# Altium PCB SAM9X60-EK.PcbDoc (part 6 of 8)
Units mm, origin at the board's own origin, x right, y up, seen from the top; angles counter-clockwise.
Board outline 150 x 125 mm, 4 copper layers (L1 - Top Layer, L2 - GND, L3 - PWR, L4 - Bottom Layer), stack 1.52 mm thick; 566 components, 500 nets, 2132 pads, 1038 vias.
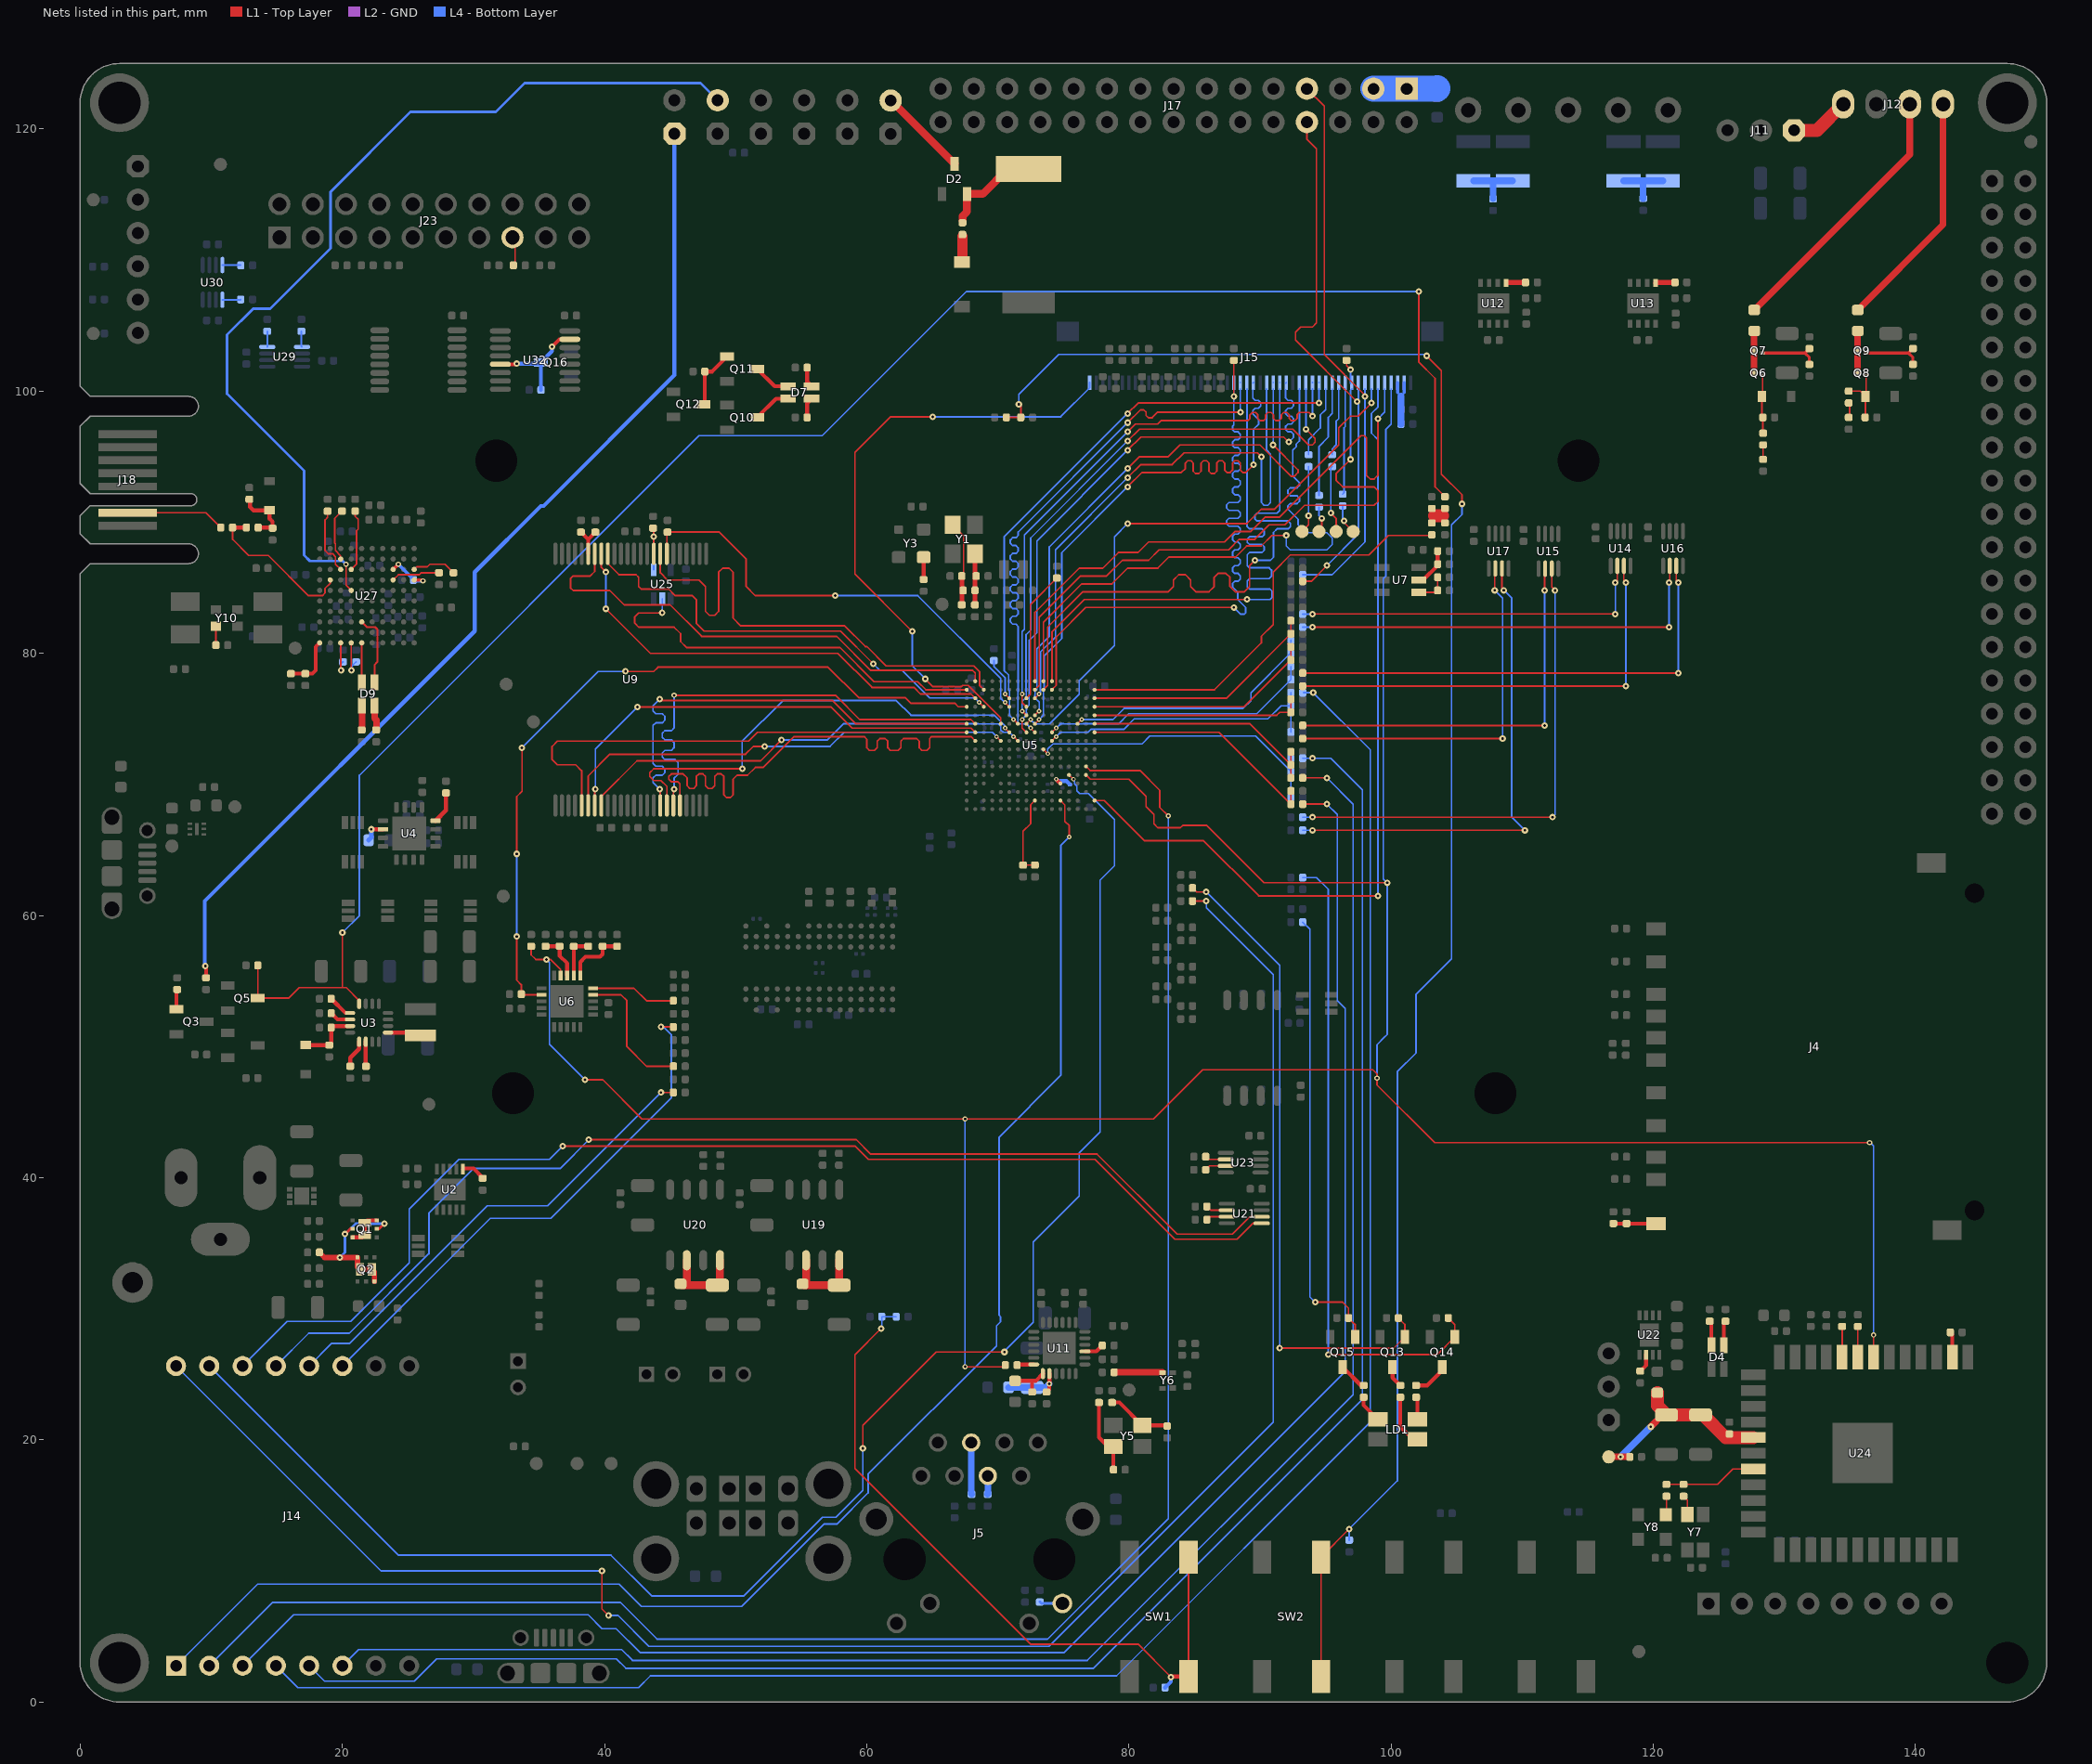
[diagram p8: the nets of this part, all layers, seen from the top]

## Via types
v1: diameter 0.5, hole 0.2, L1 - Top Layer to L4 - Bottom Layer, tented both sides, 483 vias
v2: diameter 0.5, hole 0.2, L1 - Top Layer to L4 - Bottom Layer, 268 vias
v3: diameter 0.4, hole 0.2, L1 - Top Layer to L4 - Bottom Layer, tented both sides, 145 vias
v4: diameter 0.35, hole 0.15, L1 - Top Layer to L4 - Bottom Layer, tented both sides, 121 vias
v5: diameter 0.55, hole 0.3, L1 - Top Layer to L4 - Bottom Layer, tented bottom, 16 vias
v6: diameter 0.559, hole 0.305, L1 - Top Layer to L4 - Bottom Layer, 5 vias

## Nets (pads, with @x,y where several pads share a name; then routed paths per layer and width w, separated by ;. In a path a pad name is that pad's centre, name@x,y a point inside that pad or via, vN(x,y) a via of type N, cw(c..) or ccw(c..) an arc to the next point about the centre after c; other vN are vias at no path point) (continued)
LCD_D16_ISI_nRST_PC16: J15.23 R212.1 U5.R6 | length 49.8
  L1 - Top Layer w0.125: U5.R6@74.125,77.225 74.45,77.55 74.45,81.25 76.7,83.5 v1(88,83.5) ; v1(88,99.6) R212.1@88,102.35
  L4 - Bottom Layer w0.125: v1(88,83.5) 88.5,83 88.8,83 88.9,83.1 88.9,83.5 88.3,84.1 88.3,84.675 87.9,85.075 87.9,85.325 88.075,85.5 88.325,85.5 88.5,85.675 88.5,85.925 88.325,86.1 88.075,86.1 87.9,86.275 87.9,86.525 88.075,86.7 88.325,86.7 88.5,86.875 88.5,87.125 88.325,87.3 88.075,87.3 87.9,87.475 87.9,87.725 88.075,87.9 88.325,87.9 88.5,88.075 88.5,88.325 88.325,88.5 88.075,88.5 87.9,88.675 87.9,88.925 88.075,89.1 88.325,89.1 88.5,89.275 88.5,89.525 88.325,89.7 87.625,89.7 87.45,89.875 87.45,90.125 87.625,90.3 88.325,90.3 88.5,90.475 88.5,90.725 88.325,90.9 87.625,90.9 87.45,91.075 87.45,91.325 87.625,91.5 88.325,91.5 88.5,91.675 88.5,91.925 88.325,92.1 88.075,92.1 87.9,92.275 87.9,92.525 88.075,92.7 88.325,92.7 88.5,92.875 88.5,93.125 88.325,93.3 88.075,93.3 87.9,93.475 87.9,93.725 88.075,93.9 88.325,93.9 88.5,94.075 88.5,94.325 88.325,94.5 88.075,94.5 87.9,94.675 87.9,94.925 88.075,95.1 88.325,95.1 88.5,95.275 88.5,95.525 88.325,95.7 88.075,95.7 87.9,95.875 87.9,96.125 88.075,96.3 88.325,96.3 88.5,96.475 88.5,96.725 88.325,96.9 88.075,96.9 87.9,97.075 87.9,97.325 88,97.425 J15.23@88,100.159
LCD_D17_PC17: J15.24 U5.K8 | length 44
  L1 - Top Layer w0.125: v4(72.5,74.3) U5.K8@72.825,73.975 ; v1(79.9,97.6) 80.875,98.575 81.125,98.575 81.3,98.4 81.3,98.15 81.475,97.975 81.775,97.975 82.2,98.4 v1(88.5,98.4)
  L4 - Bottom Layer w0.1: 71.55,77.1 71.525,77.075 71.525,74.725 71.65,74.6 72.2,74.6 v4(72.5,74.3)
  L4 - Bottom Layer w0.125: 71.55,77.1 71.55,82.05 71.375,82.225 71.125,82.225 70.95,82.4 70.95,82.65 71.125,82.825 71.375,82.825 71.55,83 71.55,83.25 71.375,83.425 71.125,83.425 70.95,83.6 70.95,83.85 71.125,84.025 71.375,84.025 71.55,84.2 71.55,84.45 71.375,84.625 71.125,84.625 70.95,84.8 70.95,85.05 71.125,85.225 71.375,85.225 71.55,85.4 71.55,85.65 71.375,85.825 71.125,85.825 70.95,86 70.95,86.25 71.125,86.425 71.375,86.425 71.55,86.6 71.55,86.85 71.375,87.025 71.125,87.025 70.95,87.2 70.95,87.45 71.125,87.625 71.375,87.625 71.55,87.8 71.55,88.05 71.375,88.225 71.125,88.225 70.95,88.4 70.95,88.65 71.125,88.825 71.375,88.825 71.55,89 71.55,89.25 v1(79.9,97.6) ; v1(88.5,98.4) J15.24@88.5,100.159
LCD_D18_PC18: J15.25 U5.T6 | length 46.9
  L1 - Top Layer w0.125: U5.T6@74.125,77.875 74.125,81.625 76.6,84.1 v1@89,84.1
  L4 - Bottom Layer w0.125: v1(89,84.125) 89.025,84.1 90.75,84.1 90.925,84.275 90.925,84.725 90.75,84.9 89.2,84.9 89.025,85.075 89.025,85.525 89.2,85.7 90.125,85.7 90.7,85.7 90.875,85.875 90.875,86.35 90.7,86.525 89.2,86.525 89.025,86.7 89.025,87.525 89.2,87.7 90.125,87.7 90.15,87.7 90.325,87.875 90.325,88.125 90.15,88.3 89.2,88.3 89.025,88.475 89.025,88.725 89.2,88.9 90.125,88.9 90.15,88.9 90.325,89.075 90.325,89.325 90.15,89.5 89.2,89.5 89,89.7 J15.25@89,100.159
LCD_D19_PC19: J15.26 U5.L8 | length 44
  L1 - Top Layer w0.125: U5.L8@72.825,74.625 v4(73.15,74.95) ; v1(79.9,92.7) 81,93.8 84,93.8 84.3,94.1 84.3,94.525 84.475,94.7 84.725,94.7 84.9,94.525 84.9,94.25 84.9,93.9 85.075,93.725 85.325,93.725 85.5,93.9 85.5,94.25 85.5,94.525 85.675,94.7 85.925,94.7 86.1,94.525 86.1,94.25 86.1,93.9 86.275,93.725 86.525,93.725 86.7,93.9 86.7,94.25 86.7,94.525 86.875,94.7 87.125,94.7 87.3,94.525 87.3,94.25 87.3,93.975 87.475,93.8 87.725,93.8 87.9,93.975 87.9,94.25 87.9,94.525 88.075,94.7 88.325,94.7 88.5,94.525 88.5,94.25 88.5,93.975 88.675,93.8 88.925,93.8 89.5,94.375 v1(89.5,94.4)
  L4 - Bottom Layer w0.1: 73.475,75.275 73.475,76.991
  L4 - Bottom Layer w0.125: v4(73.15,74.95) 73.475,75.275 ; 73.475,76.991 73.475,77.125 73.525,77.175 73.525,79.775 74.875,81.125 74.875,87.675 v1(79.9,92.7) ; 89.45,100.109 89.45,99.475 89.625,99.3 89.875,99.3 90.05,99.125 90.05,98.875 89.875,98.7 89.625,98.7 89.45,98.525 89.45,98.275 89.9,97.825 89.9,97.5 89.5,97.1 v1(89.5,94.4) ; J15.26@89.45,100.609 J15.26@89.5,100.659
LCD_D20_PC20: J15.28 U5.P8 | length 44
  L1 - Top Layer w0.125: U5.P8@72.825,76.575 v4(73.15,76.9) ; v1(79.9,93.4) 80.9,94.4 83.3,94.4 84.2,95.3 89.8,95.3 v1(90.1,95)
  L4 - Bottom Layer w0.125: v4(73.15,76.9) 73.25,77 73.25,80.1 74.4,81.25 74.4,87.9 v1(79.9,93.4) ; v1(90.1,95) 90.1,91.5 90.3,91.3 90.6,91.3 90.8,91.5 90.8,95.2 90.5,95.5 J15.28@90.5,100.159
LCD_D21_PC21: J15.29 U5.M8 | length 44
  L1 - Top Layer w0.125: U5.M8@72.825,75.275 v4(73.15,75.6) ; v1(79.9,94.1) 80.8,95 83,95 83.9,95.9 90,95.9 92.4,93.5 92.6,93.5 92.9,93.8 92.9,94 v1(91,95.9)
  L4 - Bottom Layer w0.1: 72.825,76.809 72.825,77.1
  L4 - Bottom Layer w0.125: 72.825,76.809 72.825,76.6 73.15,76.275 v4(73.15,75.6) ; 72.825,77.1 72.975,77.25 72.975,80.35 73.925,81.3 73.925,88.125 v1(79.9,94.1) ; v1(91,95.9) J15.29@91,100.159
LCD_D22_PC22: J15.30 U5.R7 | length 47
  L1 - Top Layer w0.125: U5.R7@73.475,77.225 73.8,77.55 73.8,82 76.5,84.7 83,84.7 83.4,85.1 83.4,85.6 83.8,86 84.3,86 84.7,85.6 84.7,85.1 85.1,84.7 86.1,84.7 86.5,85.1 86.5,85.8 86.8,86.1 87.4,86.1 87.7,85.8 87.7,85.1 88.1,84.7 88.8,84.7 89.2,85.1 89.2,86.7 v1(89.6,87.1)
  L4 - Bottom Layer w0.125: v1(89.6,87.1) 90.8,87.1 91.025,87.325 91.025,89.225 91.3,89.5 92.125,89.5 92.15,89.5 92.325,89.675 92.325,89.925 92.15,90.1 91.3,90.1 89.775,90.1 89.6,90.275 89.6,90.525 89.775,90.7 90.375,90.7 91.3,90.7 91.5,90.9 J15.30@91.5,100.159
LCD_D23_PC23: J15.31 U5.K9 | length 44
  L1 - Top Layer w0.125: v4(71.85,74.95) 71.85,74.3 U5.K9@72.175,73.975 ; v1(79.9,95.5) 80.9,96.5 91.8,96.5 92.175,96.125 v1(92.2,96.125)
  L4 - Bottom Layer w0.1: 72.175,75.509 72.175,75.691 ; 72.375,76.592 72.375,77.325 72.4,77.35
  L4 - Bottom Layer w0.125: v4(71.85,74.95) 72.175,75.275 72.175,75.509 ; 72.175,75.691 72.175,75.85 72.375,76.05 72.375,76.592 ; 72.4,77.35 72.4,81 72.975,81.575 72.975,88.575 v1(79.9,95.5) ; 91.95,100.109 91.95,99.475 92.125,99.3 92.375,99.3 92.55,99.125 92.55,98.875 92.375,98.7 92.125,98.7 91.95,98.525 91.95,98.275 92.125,98.1 92.375,98.1 92.55,97.925 92.55,97.675 92.375,97.5 92.125,97.5 91.95,97.325 91.95,97.075 92.125,96.9 92.375,96.9 92.55,96.725 92.55,96.475 v1(92.2,96.125) ; J15.31@91.95,100.609 J15.31@92,100.659
LCD_DATA_ENABLE_PC29: J15.36 U5.L10 | length 44
  L1 - Top Layer w0.125: v4(71.2,74.95) U5.L10@71.525,74.625 ; v1(79.9,98.3) 80.7,99.1 v1(94.5,99.1)
  L4 - Bottom Layer w0.1: 70.875,75.275 70.875,77.187
  L4 - Bottom Layer w0.125: 70.863,77.187 70.825,77.225 70.825,78.35 70.475,78.7 70.475,88.875 v1(79.9,98.3) ; 70.875,75.275 v4(71.2,74.95) ; v1(94.5,99.1) J15.36@94.5,100.159
LCD_HSYNC/WE_PC28: J15.35 U5.N9 | length 44
  L1 - Top Layer w0.125: v4(71.85,76.9) 71.85,76.25 U5.N9@72.175,75.925 ; v1(79.9,96.9) 80.5,97.5 82.2,97.5 82.45,97.75 89.05,97.75 89.225,97.925 89.225,98.2 89.4,98.375 89.65,98.375 89.825,98.2 89.825,97.925 90,97.75 90.25,97.75 90.425,97.925 90.425,98.2 90.6,98.375 90.85,98.375 91.025,98.2 91.025,97.925 91.2,97.75 91.45,97.75 91.625,97.925 91.625,98.2 91.8,98.375 92.05,98.375 92.225,98.2 92.225,97.925 92.4,97.75 92.65,97.75 92.825,97.925 92.825,98.2 93,98.375 93.725,98.375 v1(94,98.1)
  L4 - Bottom Layer w0.125: v4(71.85,76.9) 71.85,80.1 71.85,81.675 72.025,81.85 72.025,89.025 v1(79.9,96.9) ; v1(94,98.1) J15.35@94,100.159
LCD_ID_PD14: J15.1 U5.L12 | length 47.4
  L1 - Top Layer w0.125: v1(63.475,81.675) 59.1,86.05 59.1,95.325 61.825,98.05 v1(65.025,98.05) ; v1(64.475,78.05) 64.475,78.025 65.025,77.475 67.25,77.475 67.325,77.55 67.75,77.55 70.225,75.075 U5.L12@70.225,74.625
  L4 - Bottom Layer w0.125: v1@63.475,81.725 v1(63.475,81.675) 63.475,79.05 v1(64.475,78.05) ; v1(65.025,98.05) 74.8,98.05 77,100.25 J15.1@77,100.659
LCD_IRQ1_PC25: J15.44 U5.L9 | length 44
  L1 - Top Layer w0.125: U5.L9@72.175,74.625 v4(72.5,74.95) ; v1(79.9,89.9) 89,89.9 90.1,91 91.1,91 96,95.9 96,97.2 96.9,98.1 97.5,98.1 v1(98.5,99.1)
  L4 - Bottom Layer w0.1: v4(72.5,74.95) 72.825,74.625 73.935,74.625 76.2,76.89
  L4 - Bottom Layer w0.125: 76.2,76.89 76.2,77.9 78.9,80.6 78.9,88.9 v1(79.9,89.9) ; v1(98.5,99.1) J15.44@98.5,100.159
LCD_IRQ2_PB17: J15.45 U5.B1 | length 63.7
  L1 - Top Layer w0.125: U5.B1@77.375,68.775 78.125,68.775 81.2,65.7 85.7,65.7 89.9,61.5 v1(99,61.5)
  L4 - Bottom Layer w0.125: v1(99,61.5) 99,96.3 98.5,96.8 98.5,98.3 99,98.8 J15.45@99,100.159
LCD_ISI_ENABLE_PC24: J15.41 R213.2 U5.R8 | length 48.8
  L1 - Top Layer w0.125: U5.R8@72.825,77.225 73.15,77.55 73.15,82.75 76.3,85.9 78.3,85.9 79.5,87.1 81.5,87.1 82.3,87.9 87.6,87.9 88.4,88.7 89.6,88.7 90.7,89.8 91.9,89.8 93.4,91.3 98.7,91.3 99,91.6 99,92.4 98.7,92.7 96.3,92.7 95.8,93.2 95.8,93.7 v1(96.9,94.8) ; R213.2@96.6,102.35 96.6,101.941 v1(96.9,101.641)
  L4 - Bottom Layer w0.125: v1(96.9,94.8) 96.9,100.059 J15.41@97,100.159 ; J15.41@96.9,100.6 v1(96.9,101.641)
LCD_ISI_TWCK: J15.43 J17.7 R73.2 | length 42.8
  L1 - Top Layer w0.125: J17.7@93.568,123.07 94.9,121.738 94.9,102.8 98,99.7 v1(98,99.6)
  L4 - Bottom Layer w0.125: R73.2@93.25,86 95.5,86 98,88.5 J15.43@98,100.159
LCD_ISI_TWD: J15.42 J17.8 R64.2 | length 41.6
  L1 - Top Layer w0.125: R64.2@93.25,85.5 93.9,85.5 v2(95.1,86.7) ; J17.8@93.568,120.53 93.568,119.232 94.3,118.5 94.3,105.2 94,104.9 93.1,104.9 92.7,104.5 92.7,103.9 v1(97.39,99.209)
  L4 - Bottom Layer w0.125: v2(95.1,86.7) 97.5,89.1 J15.42@97.5,100.159
LCD_PCLK_PC30: J15.33 U5.T7 | length 47
  L1 - Top Layer w0.125: U5.T7@73.475,77.875 73.475,82.375 76.4,85.3 78.7,85.3 79.9,86.5 82.2,86.5 83.05,87.35 88.125,87.35 88.975,88.2 90.1,88.2 90.896,88.996 v1(92,88.996)
  L4 - Bottom Layer w0.125: v1(92,88.996) 92,88.2 92.3,87.9 95.1,87.9 95.5,88.3 95.5,88.8 95.1,89.2 93.5,89.2 92.9,89.8 92.9,90.225 92.125,91 92.125,91.25 92.3,91.425 92.825,91.425 93,91.6 93,91.85 92.825,92.025 92.3,92.025 92.125,92.2 92.125,92.45 92.3,92.625 92.825,92.625 93,92.8 93,93.025 92.5,93.525 92.5,95.5 92.762,95.762 92.762,95.963 93,96.2 J15.33@93,100.159
LCD_PWM_PC26: J15.46 U5.T8 | length 46.9
  L1 - Top Layer w0.125: U5.T8@72.825,77.875 72.825,83.125 76.2,86.5 78,86.5 79.2,87.7 80.7,87.7 81.5,88.5 87.3,88.5 88.1,89.3 89.3,89.3 90.4,90.4 91.5,90.4 97.7,96.6 97.95,96.6 98.125,96.425 98.125,93.575 98.4,93.3 98.7,93.3 99,93.6 v1(99,97.9)
  L4 - Bottom Layer w0.125: v1(99,97.9) 99.5,98.4 J15.46@99.5,100.159
LCD_VSYNC/CS_PC27: J15.34 U5.M9 | length 44
  L1 - Top Layer w0.125: v4@71.875,75.575 U5.M9@72.175,75.275 ; v1(79.9,96.2) 80.8,97.1 92.5,97.1 93.7,95.9 94,95.9 94.2,96.1 94.2,96.4 v1(93.5,97.1)
  L4 - Bottom Layer w0.1: 72.15,77.1 72.175,77.075 72.175,76.664 72.156,76.646
  L4 - Bottom Layer w0.125: v4(71.85,75.6) 71.85,76.339 72.156,76.646 ; 72.15,77.1 72.15,81.425 72.5,81.775 72.5,88.8 v1(79.9,96.2) ; v1(93.5,97.1) J15.34@93.5,100.159
LED1_3U: D9.2 U27.E3 | length 5.6
  L1 - Top Layer w0.15: U27.E3@21.475,82.4 21.875,82 22.5,82 22.675,81.825 22.675,79.35 22.45,79.125 D9.2@22.45,77.8
LED2_3U: D9.3 U27.E1 | length 3
  L1 - Top Layer w0.15: U27.E1@21.475,80.8 21.475,77.825 D9.3@21.5,77.8
LEFT_N: FB11.2 J12.1 | length 18.4
  L1 - Top Layer w0.5: FB11.2@135.6,106.2 142.1,112.7 J12.1@142.1,121.9
LEFT_P: FB10.2 J12.2 | length 20.6
  L1 - Top Layer w0.5: FB10.2@127.7,106.2 139.56,118.06 J12.2@139.56,121.9
MBUS_AD4_PB15: J14.1 U5.B5 | length 119.2
  L1 - Top Layer w0.125: U5.B5@74.775,68.775 75.112,68.438 75.112,67.188 75.45,66.85 v4(75.45,66)
  L4 - Bottom Layer w0.125: J14.1@7.31,2.77 13.54,9 41.1,9 42.8,7.3 50.45,7.3 56.725,13.575 57.725,13.575 60.1,15.95 60.1,17.375 69.9,27.175 69.9,28.7 70.2,29 70.2,29.4 70.1,29.5 70.1,43.1 74.8,47.8 74.8,65.35 v4(75.45,66)
MBUS_INT_PB18: J14.15 U5.E4 | length 127.8
  L1 - Top Layer w0.125: v1(59.7,19.35) 59.7,21.1 65.3,26.7 v1(70.5,26.7) ; U5.E4@75.425,70.725 v4@75.725,70.425
  L4 - Bottom Layer w0.125: J14.15@9.85,25.63 24.28,11.2 40.49,11.2 43.59,8.1 50.625,8.1 56.625,14.1 57.65,14.1 59.7,16.15 v1(59.7,19.35) ; v1(70.5,26.7) 70.5,26.781 72.7,28.981 72.7,35.1 76.2,38.6 76.2,41.9 77.8,43.5 77.8,62.7 78.9,63.8 78.9,67.325 76.925,69.3 76.25,69.3 76.025,69.525 76.025,69.875 75.85,70.05 75.85,70.25 v4@75.725,70.375
  other v4: 75.775,70.4
MBUS_MISO_PA11: J14.5 R50.1 | length 142.4
  L4 - Bottom Layer w0.125: J14.5@17.47,2.77 18.64,1.6 25.5,1.6 27.2,3.3 40.9,3.3 41.625,2.575 43,2.575 77.293,2.575 97.8,23.082 97.8,64.7 97.8,69.6 95.4,72 v2(94.001,72) R50.1@93.251,72
MBUS_MOSI_PA12: J14.6 R53.1 | length 136.1
  L1 - Top Layer w0.125: R53.1@93.251,70.5 v2(95.1,70.5)
  L4 - Bottom Layer w0.125: J14.6@20.01,2.77 21.24,4 41.3,4 42.125,3.175 43.2,3.175 76.825,3.175 97.1,23.45 97.1,68.5 v2(95.1,70.5)
MBUS_NPCS0_PA14: J14.3 R58.1 | length 141.5
  L1 - Top Layer w0.125: R58.1@93.251,68.5 v2(95.1,68.5)
  L4 - Bottom Layer w0.125: J14.3@12.39,2.77 16.27,6.65 38.75,6.65 39.8,5.6 40.875,5.6 42.7,3.775 75.075,3.775 96.5,25.2 96.5,52.9 95.9,53.5 95.9,67.7 v2(95.1,68.5)
MBUS_PWM_PB13: J14.16 R65.2 | length 144.2
  L1 - Top Layer w0.125: v1(39.8,10) 39.8,7.1 v1(40.3,6.6) ; R65.2@84.85,61.1 v2(85.9,61.1)
  L4 - Bottom Layer w0.125: J14.16@7.31,25.63 22.94,10 v1(39.8,10) ; v1(40.3,6.6) 41.025,6.6 43.375,4.25 73.9,4.25 91,21.35 91,55.5 85.9,60.6 v2(85.9,61.1)
MBUS_RST_PB14: J14.2 U5.F2 | length 142.3
  L1 - Top Layer w0.125: U5.F2@76.725,71.375 77.039,71.061 80.839,71.061 82.348,69.552 82.348,68.252 v3(83,67.6)
  L4 - Bottom Layer w0.125: J14.2@9.85,2.77 14.68,7.6 41.2,7.6 44,4.8 73.8,4.8 83,14 v3(83,67.6)
MBUS_RX: J14.14 U21.5 | length 90.5
  L1 - Top Layer w0.125: v1(36.8,42.4) 38.025,42.4 59.134,42.4 60.134,41.4 77.4,41.4 83.5,35.3 88.231,35.3 89.45,36.519 U21.5@90.125,36.519
  L4 - Bottom Layer w0.125: J14.14@12.39,25.63 15.8,29.04 20.64,29.04 25.1,33.5 25.1,37.6 28.9,41.4 35.8,41.4 v1(36.8,42.4)
MBUS_SPCK_PA13: J14.4 R56.1 | length 150.8
  L4 - Bottom Layer w0.125: J14.4@14.93,2.77 16.6,1.1 42.6,1.1 43.5,2 79.052,2 98.4,21.348 98.4,67.4 98.4,72.651 v2(94.051,77) R56.1@93.301,77
MBUS_TWCK: J14.12 R95.2 | length 36.4
  L1 - Top Layer w0.125: v2(44.3,46.5) R95.2@45.25,46.5
  L4 - Bottom Layer w0.125: J14.12@17.47,25.63 19.2,27.36 20.56,27.36 31.05,37.85 35.65,37.85 v2(44.3,46.5)
MBUS_TWD: J14.11 R90.2 | length 40.4
  L1 - Top Layer w0.125: v2(44.3,51.5) R90.2@45.25,51.5
  L4 - Bottom Layer w0.125: J14.11@20.01,25.63 31.28,36.9 35.9,36.9 45.1,46.1 45.1,50.9 44.5,51.5 v2(44.3,51.5)
MBUS_TX: J14.13 U21.6 | length 87.7
  L1 - Top Layer w0.125: v1(38.8,42.9) 59.2,42.9 60.3,41.8 77.566,41.8 83.666,35.7 87.881,35.7 89.2,37.019 U21.6@90.125,37.019
  L4 - Bottom Layer w0.125: J14.13@14.93,25.63 17.435,28.135 20.535,28.135 26.6,34.2 26.6,37.3 30,40.7 36.6,40.7 v1(38.8,42.9)
MCP23008_INT_PD17: R33.1 U5.N16 U6.7 | length 58.4
  L1 - Top Layer w0.125: v1(33.3,58.4) 33.3,55.075 33.65,54.725 R33.1@33.65,54 33.7,53.95 U6.7@35.185,53.95 ; v1(33.3,64.7) 33.3,69.075 33.7,69.475 v1(33.7,72.8) ; v1(41.6,78.625) 43.75,78.625 44.075,78.95 57.05,78.95 59.375,76.625 62.925,76.625 63.35,76.2 66.7,76.2 66.975,75.925 U5.N16@67.625,75.925
  L4 - Bottom Layer w0.125: v1(33.3,58.4) v1(33.3,64.7) ; v1(33.7,72.8) 39.525,78.625 v1(41.6,78.625)
MCP23008_TWCK: R96.2 U6.19 | length 10.4
  L1 - Top Layer w0.125: U6.19@39.115,53.95 41.25,53.95 41.7,53.5 41.7,50 43.2,48.5 R96.2@45.25,48.5
MCP23008_TWD: R92.2 U6.20 | length 6.5
  L1 - Top Layer w0.125: U6.20@39.115,54.45 42.25,54.45 43.2,53.5 R92.2@45.25,53.5
MIC2800_nRST: Q5.3 R17.1 R185.1 U3.12 | length 140.5
  L1 - Top Layer w0.125: R17.1@13.55,56.2 Q5.3@13.55,53.7 15.9,53.7 16.7,54.5 20,54.5 ; v1(20,58.7) 20,54.5 ; U3.12@21.281,53.268 21.281,53.519 20.3,54.5 20,54.5 ; v2(102.1,107.6) 102.1,102.232 103.35,100.983 103.35,92.7 R185.1@104.1,91.95
  L4 - Bottom Layer w0.125: v1(20,58.7) 21.3,60 21.3,70.7 47.2,96.6 56.6,96.6 67.6,107.6 v2(102.1,107.6)
MPU_nRST: R26.1 R185.2 R190.2 R191.2 | length 0.6
  L1 - Top Layer w1: 103.3,90.5 103.9,90.5
NAND_ALE_PD02: U5.P15 U9.17 | length 35.3
  L1 - Top Layer w0.125: U9.17@39.75,87.6 39.75,86.55 v1(40.1,86.2) ; v1(40.1,83.4) 43.5,80 57.8,80 60.4,77.4 63.6,77.4 64.1,76.9 67.95,76.9 U5.P15@68.275,76.575
  L4 - Bottom Layer w0.125: v1(40.1,83.4) v1(40.1,86.2)
NAND_CLE_PD03: U5.N14 U9.16 | length 35.4
  L1 - Top Layer w0.125: U9.16@40.25,87.6 40.25,86.85 41.1,86 42.4,86 42.6,85.8 42.6,85.1 42.8,84.9 44.9,84.9 45.4,84.4 46.7,84.4 47,84.1 47,82.3 47.6,81.7 58,81.7 v1(60.5,79.2) ; v4@68.6,76.25 U5.N14@68.925,75.925
  L4 - Bottom Layer w0.125: v1(60.5,79.2) 61,78.7 62.7,78.7 64.8,76.6 68.25,76.6 v4@68.6,76.25
  other v4: 68.57,76.25
NAND_IO0_PD06: U5.K16 U9.29 | length 38.8
  L1 - Top Layer w0.125: U9.29@38.25,68.4 38.25,71.05 37.8,71.5 36.4,71.5 36,71.9 36,72.9 36.4,73.3 51,73.3 51.675,73.975 U5.K16@67.625,73.975 67.175,73.975
NAND_IO1_PD07: U5.J12 U9.30 | length 35.4
  L1 - Top Layer w0.125: U9.30@38.75,68.4 38.75,70.65 40.4,72.3 50.75,72.3 51.35,72.9 v1(52.2,72.9) ; v4(69.9,73.65) U5.J12@70.225,73.325
  L4 - Bottom Layer w0.1: 68.509,73.975 69.575,73.975
  L4 - Bottom Layer w0.125: v1(52.2,72.9) 57.2,72.9 58.275,73.975 68.509,73.975 ; 69.575,73.975 v4(69.9,73.65)
NAND_IO2_PD08: U5.K15 U9.31 | length 35.4
  L1 - Top Layer w0.125: U9.31@39.25,68.4 39.25,69.6 v1(39.3,69.65) ; v1(42.5,75.9) 57.3,75.9 58.9,74.3 67.95,74.3 U5.K15@68.275,73.975
  L4 - Bottom Layer w0.125: v1(39.3,69.65) 39.3,72.7 v1(42.5,75.9)
NAND_IO3_PD09: U5.J10 U9.32 | length 35.5
  L1 - Top Layer w0.125: U9.32@39.75,68.4 39.75,69.077 42.473,71.8 51.9,71.8 v1(53.5,73.4) ; v4(71.2,73.65) U5.J10@71.525,73.325
  L4 - Bottom Layer w0.1: 68.509,74.625 70.05,74.625 70.225,74.45 70.225,74.165 70.415,73.975 70.425,73.975 70.875,73.975
  L4 - Bottom Layer w0.125: v1(53.5,73.4) 57,73.4 58.225,74.625 68.509,74.625 ; 70.875,73.975 v4(71.2,73.65)
NAND_IO4_PD10: U5.L16 U9.41 | length 36.1
  L1 - Top Layer w0.125: v1(44.2,69.65) 44.25,69.6 U9.41@44.25,68.4 ; v1(44.2,76.5) 44.3,76.4 57.4,76.4 59.175,74.625 U5.L16@67.625,74.625 66.925,74.625
  L4 - Bottom Layer w0.125: v1(44.2,69.65) 43.7,70.15 43.7,70.5 43.9,70.7 44.4,70.7 44.6,70.9 44.6,71.2 44.4,71.4 43.9,71.4 43.7,71.6 43.7,74.5 43.9,74.7 44.4,74.7 44.6,74.9 44.6,75.2 44.4,75.4 43.9,75.4 43.7,75.6 43.7,76 v1(44.2,76.5)
NAND_IO5_PD11: U5.K11 U9.42 | length 35.4
  L1 - Top Layer w0.125: U9.42@44.75,68.4 44.75,69.85 44.3,70.3 43.75,70.3 43.45,70.6 43.45,70.9 43.75,71.2 v1(50.5,71.2) ; v4@70.525,74.3 70.538,74.288 70.85,73.975 U5.K11@70.875,73.975
  L4 - Bottom Layer w0.1: 68.5,75.275 69.115,75.275 69.341,75.275
  L4 - Bottom Layer w0.125: v1(50.5,71.2) 50.5,73.3 53.6,76.4 62.25,76.4 63.375,75.275 68.5,75.275 ; 69.341,75.275 69.725,75.275 70.525,74.475 v4@70.525,74.3
  other v4: 70.55,74.3
NAND_IO6_PD12: U5.L15 U9.43 | length 35.4
  L1 - Top Layer w0.125: U9.43@45.25,68.4 45.25,69.6 v1(45.3,69.65) ; v3(45.3,76.8) 57.6,76.8 59.45,74.95 67.95,74.95 U5.L15@68.275,74.625
  L4 - Bottom Layer w0.125: v1(45.3,69.65) 45.3,70.475 45.6,70.775 45.6,71.675 45.375,71.9 44.6,71.9 44.4,72.1 44.4,72.4 44.6,72.6 45.1,72.6 45.3,72.8 45.3,73.2 45.1,73.4 44.6,73.4 44.4,73.6 44.4,73.9 44.6,74.1 45.1,74.1 45.3,74.3 v3(45.3,76.8)
NAND_IO7_PD13: U5.J15 U9.44 | length 38.4
  L1 - Top Layer w0.125: U9.44@45.75,68.4 45.75,70.05 45.6,70.2 45.1,70.2 44.9,70.4 44.9,70.6 45.1,70.8 46,70.8 46.3,70.5 46.3,69.9 46.5,69.7 46.8,69.7 47,69.9 47,70.6 47.2,70.8 47.5,70.8 47.7,70.6 47.7,69.9 47.9,69.7 48.2,69.7 48.4,69.9 48.4,70.6 48.6,70.8 48.9,70.8 49.1,70.6 49.1,69.2 49.3,69 49.6,69 49.8,69.2 49.8,70.4 50.1,70.7 50.9,70.7 51.5,71.3 52.1,71.3 54.45,73.65 59.8,73.65 60,73.45 60,72.8 60.2,72.6 60.6,72.6 60.8,72.8 60.8,73.3 61,73.5 61.4,73.5 61.6,73.3 61.6,72.8 61.8,72.6 62.4,72.6 62.6,72.8 62.6,73.3 62.8,73.5 63.8,73.5 64,73.3 64,72.8 64.2,72.6 64.6,72.6 64.8,72.8 64.8,73.5 64.95,73.65 67.95,73.65 U5.J15@68.275,73.325
NAND_nCS_PD04: U5.R16 U25.2 | length 31.6
  L1 - Top Layer w0.125: v1(44.4,83.087) 42.587,83.087 42.3,82.8 42.3,82.3 42.6,82 45.3,82 45.8,81.5 45.8,80.9 46.25,80.45 57.95,80.45 60.554,77.846 63.879,77.846 64.5,77.225 U5.R16@67.625,77.225
  L4 - Bottom Layer w0.125: v1(44.4,83.087) U25.2@44.4,84.175
NAND_nCS_PD04_enabled: R114.1 U9.9 U25.4 | length 4.5
  L1 - Top Layer w0.125: R114.1@43.7,89.55 43.75,89.5 v1(43.75,88.9) U9.9@43.75,87.6
  L4 - Bottom Layer w0.125: U25.4@43.75,86.375 v1(43.75,88.9)
NAND_nRE_PD00: U5.R14 U9.8 | length 38.4
  L1 - Top Layer w0.125: U9.8@44.25,87.6 44.25,86.15 44.8,85.6 47.2,85.6 47.7,85.1 47.7,83.2 48,82.9 48.4,82.9 48.7,83.2 48.7,86.2 49,86.5 49.5,86.5 49.8,86.2 49.8,82.7 50.4,82.1 58.313,82.1 59.9,80.513 60.019,80.513 61.481,79.05 68.175,79.05 68.6,78.625 68.6,77.55 U5.R14@68.925,77.225
NAND_nWE_PD01: U5.T15 U9.18 | length 38.3
  L1 - Top Layer w0.125: U9.18@39.25,87.6 39.25,86.25 38.9,85.9 37.6,85.9 37.4,85.7 37.4,85 37.6,84.8 40.4,84.8 41.5,83.7 45,83.7 47.4,81.3 57.7,81.3 60.3,78.7 68.075,78.7 68.275,78.5 U5.T15@68.275,77.875
NAND_RB_PD05: R115.1 U5.N11 U9.7 | length 35.4
  L1 - Top Layer w0.125: U9.7@44.75,87.6 44.75,89.2 R115.1@44.8,89.25 48.75,89.25 50.8,87.2 50.8,85.1 51.5,84.4 v1(57.6,84.4) ; v4(70.55,76.25) U5.N11@70.875,75.925
  L4 - Bottom Layer w0.1: 70.225,76.575 70.225,77.1
  L4 - Bottom Layer w0.125: v1(57.6,84.4) 63.9,84.4 70.225,78.075 70.225,77.1 ; 70.225,76.575 v4(70.55,76.25)
NetC17_1: C17.1 U3.14 | length 1.6
  L1 - Top Layer w0.3: C17.1@19.15,52.55 19.632,52.068 U3.14@20.581,52.068
NetC18_1: C18.1 U3.2 | length 1.9
  L1 - Top Layer w0.3: U3.2@21.781,50.368 21.781,48.519 C18.1@21.8,48.5
NetC19_1: C19.1 D1.1 R11.2 U3.15 | length 4.7
  L1 - Top Layer w0.3: D1.1@17.2,50.115 R11.2@19,50.115 19.065,50.115 19.15,50.2 C19.1@19.15,51.45 19.268,51.568 U3.15@20.581,51.568
NetC20_1: C20.1 U3.13 | length 1.9
  L1 - Top Layer w0.3: C20.1@19.15,53.65 20.232,52.568 U3.13@20.581,52.568
NetC23_1: C23.1 D2.2 R20.2 | length 7.7
  L1 - Top Layer w0.6: R20.2@67.3,113 67.3,113.35 67.65,113.7 D2.2@67.65,115.05 68.85,115.05 70.75,116.95 C23.1@72.35,116.95
NetC24_1: C24.1 R21.2 R27.2 Y1.1 | length 6.5
  L1 - Top Layer w0.1: Y1.1@66.549,89.805 67.4,88.954 67.4,86.05 C24.1@67.25,85.9
  L1 - Top Layer w0.35: R27.2@67.25,83.7 C24.1@67.25,85.9
NetC25_1: C25.1 R21.1 R91.2 Y1.3 | length 3.9
  L1 - Top Layer w0.35: R91.2@68.25,83.7 68.25,85.9 68.25,87.594 Y1.3@68.251,87.595
NetC28_2: C28.2 R25.1 U5.D5 | length 1.7
  L1 - Top Layer w0.3: v4(74.45,70.4) U5.D5@74.775,70.075
  L4 - Bottom Layer w0.3: v4(74.45,70.4) 74.588,70.262 C28.2@74.925,70.262 75.225,70.262 R25.1@75.5,69.987
NetC62_2: C62.2 R119.2 U5.B8 | length 6.2
  L1 - Top Layer w0.125: R119.2@72.825,63.85 C62.2@71.925,63.85 71.925,66.425 72.5,67 72.5,68.45 U5.B8@72.825,68.775
NetC83_1: C83.1 J5.5 | length 1.4
  L4 - Bottom Layer w0.5: C83.1@69.215,15.85 69.235,15.87 J5.5@69.235,17.25
NetC84_1: C84.1 J5.4 | length 4
  L4 - Bottom Layer w0.5: J5.4@67.965,19.79 67.965,15.885 C84.1@68,15.85
NetC85_1: C85.1 C86.1 U11.1 | length 3.2
  L1 - Top Layer w0.3: C85.1@71.315,24.5 72.7,24.5 ; C86.1@72.615,23.65 72.615,24.415 72.7,24.5 ; U11.1@73.435,25.05 72.885,24.5 72.7,24.5
NetC87_1: C87.1 C88.1 FB2.1 U11.2 | length 4.7
  L1 - Top Layer w0.3: C88.1@73.715,23.65 73.915,23.85 v3(73.915,24.275) 73.935,24.295 U11.2@73.935,25.05
  L4 - Bottom Layer w0.5: FB2.1@70.815,24 C87.1@72.615,24 73.64,24 v3(73.915,24.275)
NetC91_1: C91.1 R126.2 Y5.1 | length 4.9
  L1 - Top Layer w0.3: R126.2@78.715,22.85 79.265,22.85 Y5.1@81.015,21.1 82.865,21.1 C91.1@82.915,21.05
NetC92_1: C92.1 R128.2 Y5.3 | length 5.9
  L1 - Top Layer w0.3: R128.2@77.715,22.85 77.715,20.185 78.5,19.4 Y5.3@78.815,19.4 ; C92.1@78.815,17.725 Y5.3@78.815,19.4 ; Y5.3@78.815,19.5 Y5.3@78.815,19.4
NetC94_2: C94.2 R134.1 R136.2 | length 4.4
  L4 - Bottom Layer w0.5: R134.1@106.275,116.05 107.775,116.05 ; C94.2@107.775,114.675 107.775,116.05 ; R136.2@109.275,116.05 107.775,116.05
NetC98_2: C98.2 R137.1 R139.2 | length 4.4
  L4 - Bottom Layer w0.5: R137.1@117.725,116.05 119.225,116.05 ; C98.2@119.225,114.7 119.225,116.05 ; R139.2@120.725,116.05 119.225,116.05
NetC113_1: C113.1 FB6.1 U19.6 U19.8 | length 6.6
  L1 - Top Layer w0.6: U19.6@55.365,33.7 55.365,31.965 55.2,31.8 C113.1@57.9,31.8 57.905,31.805 U19.8@57.905,33.7
NetC119_1: C119.1 FB8.1 U20.6 U20.8 | length 6.6
  L1 - Top Layer w0.6: FB8.1@45.9,31.8 FB8.1@46.2,31.8 ; U20.6@46.265,33.7 46.265,31.865 FB8.1@46.2,31.8 ; U20.8@48.805,33.7 48.805,32.005 C119.1@48.6,31.8 FB8.1@46.2,31.8
NetC128_2: C128.2 U22.6 | length 1.4
  L1 - Top Layer w0.3: C128.2@119,25.25 119.45,25.7 U22.6@119.45,26.5
NetC130_1: C130.1 C131.1 C132.1 FB9.2 R162.2 U24.18 VDD_WILC.1 | length 15.8
  L1 - Top Layer w0.5: VDD_WILC.1@116.6,18.7 v1(117.5,18.7) R162.2@118.2,18.7 ; v1(119.8,21) 120.7,21.9 C132.1@121,21.9
  L1 - Top Layer w1: FB9.2@120.3,23.6 120.3,22.6 C132.1@121,21.9 123.8,21.9 125.53,20.17 U24.18@127.62,20.17
  L4 - Bottom Layer w0.5: v1(117.5,18.7) v1(119.8,21)
NetC141_1: C141.1 R177.2 | length 1.1
  L1 - Top Layer w0.125: R177.2@128.375,94.8 C141.1@128.375,95.9
NetC141_2: C141.2 D5.1 Q6.1 R176.1 | length 4.5
  L1 - Top Layer w0.125: Q6.1@128.325,101.213 128.325,99.64 D5.1@128.285,99.6 128.285,98.065 R176.1@128.35,98 128.35,96.825 C141.2@128.375,96.8
NetC142_1: C142.1 R181.2 | length 1.1
  L1 - Top Layer w0.125: R181.2@134.975,98 C142.1@134.975,99.1
NetC142_2: C142.2 D6.1 Q8.1 R180.1 | length 4.7
  L1 - Top Layer w0.125: C142.2@134.9,100 135.785,100 D6.1@136.185,99.6 ; Q8.1@136.225,101.212 136.225,99.64 D6.1@136.185,99.6 ; R180.1@136.25,98 136.185,98.065 D6.1@136.185,99.6
NetC143_1: C143.1 R186.2 R192.2 SW1.1 SW1.2 | length 55.7
  L1 - Top Layer w0.125: v2(61.1,28.5) 59.1,26.5 59.1,17.8 72.487,4.413 80.687,4.413 v2(83.2,1.9) ; SW1.2@84.55,1.95 SW1.1@84.55,11.05
  L1 - Top Layer w0.3: v2(83.2,1.9) 83.25,1.95 SW1.2@84.55,1.95
  L4 - Bottom Layer w0.125: v2(61.1,28.5) 61.15,28.55 R186.2@61.15,29.4 R192.2@62.25,29.4
  L4 - Bottom Layer w0.3: C143.1@82.75,1.1 83.2,1.55 v2(83.2,1.9)
NetC144_1: C144.1 R194.1 R197.2 SW2.1 SW2.2 | length 142.5
  L1 - Top Layer w0.125: R197.2@70.65,98 R194.1@71.75,98 71.75,98.85 v1(71.6,99) ; SW2.2@94.65,1.95 SW2.1@94.65,11.05 v2(96.8,13.2) ; v1(102.7,102.7) 103.825,101.575 103.825,93.675 105.4,92.1 v2(105.4,91.4)
  L4 - Bottom Layer w0.125: v1(71.6,99) 71.6,99.754 74.646,102.8 102.6,102.8 v1(102.7,102.7) ; C144.1@96.8,12.35 v2(96.8,13.2) 100.475,16.875 100.475,48.1 101.9,49.525 101.9,54 104.6,56.7 104.6,89.5 104.6,89.8 105.4,90.6 v2(105.4,91.4)
NetC148_2: C148.2 U27.C8 | length 5.2
  L1 - Top Layer w0.125: C148.2@18.875,90.85 18.875,90.375 18.675,90.175 18.675,87.85 18.925,87.6 19.25,87.6 19.475,87.375 19.475,86.8 U27.C8@19.875,86.4
NetC149_2: C149.2 D8.1 R237.2 R238.1 | length 4.7
  L1 - Top Layer w0.3: R237.2@12.95,91.65 12.95,91.175 13.215,90.91 D8.1@14.45,90.91 14.45,90.275 14.675,90.05 C149.2@14.675,89.55 14.625,89.6 R238.1@13.575,89.6
NetC150_1: C150.1 R240.2 U27.A1 | length 4.2
  L1 - Top Layer w0.3: R240.2@16.075,78.45 C150.1@17.175,78.45 17.725,78.45 17.975,78.7 17.975,80.5 U27.A1@18.275,80.8
NetD2_3: D2.3 J2.2 | length 6.9
  L1 - Top Layer w0.6: J2.2@61.825,122.17 61.88,122.17 D2.3@66.7,117.35
NetD3_2: D3.2 R20.1 | length 2
  L1 - Top Layer w0.8: D3.2@67.25,109.85 67.3,109.9 R20.1@67.3,111.8
NetD4_1: D4.1 R160.1 | length 1.9
  L1 - Top Layer w0.3: R160.1@124.3,29.05 124.425,28.925 D4.1@124.425,27.2
NetD4_4: D4.4 R161.1 | length 1.9
  L1 - Top Layer w0.3: D4.4@125.375,27.2 125.375,28.925 R161.1@125.5,29.05
NetD7_1: D7.1 R188.2 | length 1.6
  L1 - Top Layer w0.3: R188.2@55.45,101.8 55.45,100.725 D7.1@55.8,100.375
NetD7_2: D7.2 Q11.3 | length 2.9
  L1 - Top Layer w0.3: Q11.3@51.65,101.7 52.975,100.375 D7.2@54,100.375
NetD7_3: D7.3 Q10.3 | length 2.9
  L1 - Top Layer w0.3: Q10.3@51.65,98 53.075,99.425 D7.3@54,99.425
NetD7_4: D7.4 R187.2 | length 1.6
  L1 - Top Layer w0.3: R187.2@55.45,98 55.45,99.075 D7.4@55.8,99.425
NetD9_1: D9.1 R246.2 | length 1.9
  L1 - Top Layer w0.5: D9.1@22.45,76 22.45,75.05 22.6,74.9 22.6,74.175 R246.2@22.575,74.15
NetD9_4: D9.4 R249.2 | length 1.9
  L1 - Top Layer w0.5: R249.2@21.475,74.15 21.5,74.175 D9.4@21.5,76
NetFB10_1: FB10.1 Q6.3 Q7.3 | length 3.2
  L1 - Top Layer w0.5: Q6.3@127.675,101.4 127.675,104.575 FB10.1@127.7,104.6
NetFB11_1: FB11.1 Q8.3 Q9.3 | length 3.2
  L1 - Top Layer w0.5: Q8.3@135.575,101.4 135.575,104.575 FB11.1@135.6,104.6
NetFB12_2: FB12.2 J17.1 J17.3 | length 4.9
  L4 - Bottom Layer w2: J17.3@98.648,123.07 J17.1@101.188,123.07 103.47,123.07 103.5,123.1
NetJ3_1: J3.1 R18.1 | length 79.1
  L1 - Top Layer w0.3: v1(9.55,56.15) 9.6,56.1 R18.1@9.6,55.4
  L4 - Bottom Layer w0.3: v1@9.5,56.3 9.5,61.1 30.1,81.7 30.1,86.2 35.15,91.25 35.35,91.25 45.325,101.225 J3.1@45.325,119.65
NetJ4_11: J4.11 R107.1 R118.2 | length 3.3
  L1 - Top Layer w0.3: R107.1@116.95,36.5 J4.11@120.2,36.5
NetJ5_12: J5.12 R125.2 | length 1.8
  L4 - Bottom Layer w0.2: R125.2@73.2,7.65 73.33,7.52 J5.12@74.925,7.52
NetJ11_1: J11.1 J12.4 | length 4.6
  L1 - Top Layer w1: J11.1@130.74,119.9 132.48,119.9 J12.4@134.48,121.9
NetJ15_37: J15.37 R208.2 | length 5.5
  L4 - Bottom Layer w0.125: R208.2@93.7,95.15 93.7,96.3 94.6,97.2 94.6,98.2 95,98.6 J15.37@95,100.159
NetJ15_38: J15.38 R209.2 | length 8.5
  L4 - Bottom Layer w0.125: R209.2@94.5,92.05 94.5,95.8 95.2,96.5 95.2,98 95.5,98.3 J15.38@95.5,100.159
NetJ15_39: J15.39 R210.2 | length 5.2
  L4 - Bottom Layer w0.125: R210.2@95.5,95.15 95.5,95.6 95.8,95.9 95.8,97.7 96,97.9 J15.39@96,100.159
NetJ15_40: J15.40 R211.2 | length 8.1
  L4 - Bottom Layer w0.125: R211.2@96.3,92.15 96.4,92.25 96.4,97.2 96.5,97.3 J15.40@96.5,100.159
NetJ15_48: J15.48 J15.49 R214.1 R217.1 | length 3.6
  L4 - Bottom Layer w0.25: 100.5,99.9 J15.48@100.5,100.659 ; 101,99.9 J15.49@101,100.659
  L4 - Bottom Layer w0.55: R217.1@100.75,97.5 R214.1@100.75,98.6 100.75,99.625
NetJ19_2: J19.2 U27.D6 | length 73.3
  L1 - Top Layer w0.1: v3(20.275,86.8) 20.275,85.2 U27.D6@20.675,84.8
  L4 - Bottom Layer w0.2: v3(20.275,86.8) 20.025,87.05 17.525,87.05 17.075,87.5 17.075,93.925 11.2,99.8 11.2,104.3 13.2,106.3 14.5,106.3 19.1,110.9 19.1,115.2 25.2,121.3 31.7,121.3 33.895,123.495 47.32,123.495 J19.2@48.625,122.19
NetJ23_15: J23.15 R265.2 | length 2.1
  L1 - Top Layer w0.125: R265.2@33.18,109.6 J23.15@33.18,111.73
NetL1_1: L1.1 U3.5 | length 2.3
  L1 - Top Layer w0.3: U3.5@23.481,51.068 L1.1@25.732,51.068
NetLD1_1: LD1.1 R203.2 | length 2.2
  L1 - Top Layer w0.3: R203.2@97.9,23.25 97.9,22.65 LD1.1@99,21.55
NetLD1_3: LD1.3 R199.2 | length 3.9
  L1 - Top Layer w0.3: R199.2@100.7,23.25 100.7,21 101.65,20.05 LD1.3@102,20.05
NetLD1_4: LD1.4 R201.2 | length 1.7
  L1 - Top Layer w0.3: R201.2@101.9,23.25 102,23.15 LD1.4@102,21.55
NetQ1_2: Q1.2 Q1.5 Q2.3 Q2.6 Q2.7 Q2.8 R3.2 | length 12.8
  L1 - Top Layer w0.2: v1(20.2,35.7) 20.6,36.1 Q1.2@20.788,36.1 ; Q1.5@22.613,36.1 22.8,36.1 v1(23.2,36.5)
  L1 - Top Layer w0.4: R3.2@18.25,34.3 18.637,33.913 Q2.6@21.15,33.913 21.15,33.195 Q2.7@21.345,33 Q2.8@22.255,33 22.45,32.805 Q2.3@22.45,32.087
  L4 - Bottom Layer w0.2: v1(19.8,33.9) 20.2,34.3 v1(20.2,35.7) 21,36.5 v1(23.2,36.5)
NetQ1_3: Q1.3 Q1.6 Q1.7 Q1.8 | length 2.9
  L1 - Top Layer w0.3: Q1.3@20.788,35.45 21.505,35.45 21.7,35.645 Q1.7@21.7,36.555 21.895,36.75 Q1.6@22.613,36.75
NetQ3_1: Q3.1 R19.1 | length 1.5
  L1 - Top Layer w0.3: Q3.1@7.35,52.85 7.35,54.3 R19.1@7.4,54.35
NetQ7_1: Q7.1 R178.2 R179.2 | length 4.7
  L1 - Top Layer w0.22: Q7.1@128.325,102.912 131.562,102.912 ; R178.2@131.9,102.05 131.9,102.575 131.562,102.912 ; R179.2@131.9,103.25 131.562,102.912
NetQ9_1: Q9.1 R182.2 R183.2 | length 4.7
  L1 - Top Layer w0.22: Q9.1@136.225,102.913 139.463,102.912 ; R182.2@139.8,102.05 139.8,102.575 139.463,102.912 ; R183.2@139.8,103.25 139.463,102.912
NetQ11_1: Q11.1 Q12.3 R189.1 | length 4.7
  L1 - Top Layer w0.3: Q12.3@47.55,99 47.65,99.1 R189.1@47.65,101.5 48.2,101.5 Q11.1@49.35,102.65
NetQ13_1: Q13.1 R195.2 R196.1 | length 49.9
  L1 - Top Layer w0.125: R195.2@84.85,62.1 85.15,61.8 v2(85.9,61.8) ; v1(91.5,27) 100.2,27 Q13.1@101.05,27.85 101.05,28.8 R196.1@100.55,29.3
  L4 - Bottom Layer w0.125: v2(85.9,61.8) 91.5,56.2 v1(91.5,27)
NetQ13_3: Q13.3 R199.1 | length 1.6
  L1 - Top Layer w0.3: Q13.3@100.1,25.55 100.1,24.75 R199.1@100.7,24.15
NetQ14_1: Q14.1 R200.2 R202.1 | length 49.6
  L1 - Top Layer w0.125: v1(95.2,26.5) 103.5,26.5 Q14.1@104.85,27.85 104.85,28.8 R202.1@104.35,29.3
  L4 - Bottom Layer w0.125: R200.2@93.25,62.9 94.3,62.9 95.2,62 v1@95.2,26.6
NetQ14_3: Q14.3 R201.1 | length 2.7
  L1 - Top Layer w0.3: R201.1@101.9,24.15 102.75,24.15 103.9,25.3 Q14.3@103.9,25.55
NetQ15_1: Q15.1 R206.2 R207.1 | length 34.5
  L1 - Top Layer w0.125: v1(94.2,30.5) 96.3,30.5 96.75,30.05 R207.1@96.75,29.3 97.25,28.8 Q15.1@97.25,27.85
  L4 - Bottom Layer w0.125: R206.2@93.25,59.5 93.8,58.95 93.8,30.9 v1(94.2,30.5)
NetQ15_3: Q15.3 R203.1 | length 2.2
  L1 - Top Layer w0.3: Q15.3@96.3,25.55 97.7,24.15 R203.1@97.9,24.15
NetQ16_3: Q16.3 R270.2 U32.5 U32.15 | length 8.4
  L1 - Top Layer w0.3: U32.5@32.05,102.053 33.253,102.053 v1(33.3,102.1) ; v1(36,103.4) 36.558,103.958 U32.15@37.35,103.958
  L4 - Bottom Layer w0.3: v1(33.3,102.1) 35.05,102.1 Q16.3@35.15,102.2 R270.2@35.15,100.1 ; Q16.3@35.15,102.2 36,103.05 v1(36,103.4)
NetR6_1: R6.1 U2.6 | length 1.9
  L1 - Top Layer w0.3: U2.6@29.2,40.65 29.25,40.7 30,40.7 30.7,40 R6.1@30.7,39.95
NetR13_1: R13.1 U4.16 | length 2.5
  L1 - Top Layer w0.35: U4.16@27.1,67.225 27.9,68.025 R13.1@27.9,69.35
NetR14_2: R14.2 U4.6 | length 1.8
  L1 - Top Layer w0.35: v1(22.2,66.575) U4.6@23.1,66.575
  L4 - Bottom Layer w0.35: R14.2@22,65.75 22.2,65.95 v1(22.2,66.575)
NetR22_2: R22.2 U5.P9 | length 10.4
  L1 - Top Layer w0.125: U5.P9@72.175,76.575 72.49,76.89 72.49,83.728 R22.2@74.7,85.938
NetR23_2: R23.2 U5.P11 | length 3.4
  L1 - Top Layer w0.125: v4(70.55,76.9) U5.P11@70.875,76.575
  L4 - Bottom Layer w0.125: R23.2@69.7,79.45 69.7,79 70.55,78.15 v4(70.55,76.9)
NetR26_2: R26.2 U5.R1 | length 33.3
  L1 - Top Layer w0.125: U5.R1@77.375,77.225 78.128,77.225 86.525,77.225 90.1,80.8 90.1,81.3 91,82.2 91,86.2 92.3,87.5 98.3,87.5 99.8,89 103.05,89 R26.2@103.1,89.05
NetR29_1: R29.1 U3.1 | length 2.2
  L1 - Top Layer w0.3: R29.1@20.6,48.5 20.6,49.15 21.281,49.831 U3.1@21.281,50.368
NetR35_1: R35.1 R47.2 U6.3 | length 3.6
  L1 - Top Layer w0.3: R35.1@35.5,57.65 35.506,57.656 R47.2@36.569,57.656 36.569,56.931 37.15,56.35 U6.3@37.15,55.415
NetR36_1: R36.1 R48.2 U6.2 | length 3.3
  L1 - Top Layer w0.3: U6.2@37.65,55.415 R48.2@37.65,57.65 R36.1@38.75,57.65
NetR37_1: R37.1 R49.2 U6.1 | length 4.7
  L1 - Top Layer w0.3: U6.1@38.15,55.415 38.15,56.45 38.55,56.85 39.65,56.85 39.85,57.05 R37.1@39.85,57.65 R49.2@40.95,57.65
NetR97_1: R97.1 R105.1 U7.4 | length 2.5
  L1 - Top Layer w0.125: U7.4@102.1,84.65 103.4,84.65 R97.1@103.55,84.8 R105.1@103.55,85.8
NetR98_1: R98.1 R104.1 U7.5 | length 3
  L1 - Top Layer w0.3: U7.5@102.1,85.6 102.45,85.6 103.55,86.7 R104.1@103.55,86.8 R98.1@103.55,87.8
NetR116_1: R116.1 R117.2 U9.19 | length 2.7
  L1 - Top Layer w0.3: R116.1@38.2,89.25 38.75,88.7 ; U9.19@38.75,87.6 38.75,88.7 ; R117.2@39.3,89.25 38.75,88.7
NetR124_2: R124.2 U11.9 | length 1.5
  L1 - Top Layer w0.3: U11.9@76.635,26.75 77.515,26.75 R124.2@77.965,27.2
NetR130_1: R130.1 U11.24 | length 1.3
  L1 - Top Layer w0.3: R130.1@71.465,25.7 71.515,25.75 U11.24@72.735,25.75
NetR132_1: R132.1 Y6.3 | length 3.7
  L1 - Top Layer w0.5: R132.1@78.865,25.15 Y6.3@82.575,25.15
NetR135_2: R135.2 U12.5 | length 1.5
  L1 - Top Layer w0.4: U12.5@108.825,108.25 108.875,108.3 R135.2@110.3,108.3
NetR138_2: R138.2 U13.5 | length 1.5
  L1 - Top Layer w0.4: U13.5@120.175,108.25 120.225,108.3 R138.2@121.65,108.3
NetR140_1: R140.1 U14.2 | length 27.7
  L1 - Top Layer w0.125: v2(94,83) v2(117.1,83) ; v2(117.1,85.4) 117.25,85.55 U14.2@117.25,86.675
  L4 - Bottom Layer w0.125: R140.1@93.25,83 v2(94,83) ; v2(117.1,83) v2(117.1,85.4) v2@117.2,85.5
NetR141_1: R141.1 U15.2 | length 30.4
  L1 - Top Layer w0.125: R141.1@93.25,74.5 v2(111.7,74.5) ; v2(111.7,84.8) 111.7,86.415 U15.2@111.75,86.465
  L4 - Bottom Layer w0.125: v2(111.7,74.5) v2(111.7,84.8)
NetR142_1: R142.1 U14.3 | length 34
  L1 - Top Layer w0.125: R142.1@93.25,77.5 v2(117.9,77.5) ; U14.3@117.75,86.675 117.75,85.55 v2(117.9,85.4)
  L4 - Bottom Layer w0.125: v2@117.8,85.5 v2(117.9,85.4) v2(117.9,77.5)
NetR143_1: R143.1 U15.3 | length 38.2
  L1 - Top Layer w0.125: v2(94,67.5) v2(112.3,67.5) ; U15.3@112.25,86.465 112.25,85.05 v2(112.5,84.8)
  L4 - Bottom Layer w0.125: R143.1@93.25,67.5 v2(94,67.5) ; v2(112.3,67.5) 112.5,67.7 v2(112.5,84.8)
NetR144_1: R144.1 U16.2 | length 32.8
  L1 - Top Layer w0.125: v2(94,82) v2(121.2,82) ; v2(121.2,85.4) 121.25,85.45 U16.2@121.25,86.675
  L4 - Bottom Layer w0.125: R144.1@93.25,82 v2(94,82) ; v2(121.2,82) v2(121.2,85.4) v2@121.3,85.5
NetR145_1: R145.1 U17.2 | length 28.5
  L1 - Top Layer w0.125: R145.1@93.25,73.5 v2(108.5,73.5) ; v2(107.9,84.81) 107.9,86.425 U17.2@107.95,86.475
  L4 - Bottom Layer w0.125: v2(107.9,84.81) 108.5,84.21 v2(108.5,73.5)
NetR146_1: R146.1 U16.3 | length 37
  L1 - Top Layer w0.125: R146.1@93.25,78.5 v2(121.9,78.5) ; U16.3@121.75,86.675 121.75,85.55 v2(121.9,85.4)
  L4 - Bottom Layer w0.125: v2@121.8,85.5 v2(121.9,85.4) v2(121.9,78.5)
NetR147_1: R147.1 U17.3 | length 37.6
  L1 - Top Layer w0.125: v2(94,66.5) v2(110.2,66.5) ; U17.3@108.45,86.475 108.45,84.96 v2(108.6,84.81)
  L4 - Bottom Layer w0.125: R147.1@93.25,66.5 v2(94,66.5) ; v2(108.6,84.81) 109.2,84.21 109.2,67.5 v2(110.2,66.5)
NetR149_2: R149.2 Y3.3 | length 1.7
  L1 - Top Layer w0.35: R149.2@64.337,85.638 64.34,85.64 Y3.3@64.34,87.333
NetR156_1: R156.1 U21.2 | length 1.6
  L1 - Top Layer w0.125: R156.1@85.95,37.8 86.231,37.519 U21.2@87.475,37.519
NetR157_1: R157.1 U21.3 | length 1.6
  L1 - Top Layer w0.125: R157.1@85.95,36.8 86.169,37.019 U21.3@87.475,37.019
NetR158_1: R158.1 U23.2 | length 1.6
  L1 - Top Layer w0.125: R158.1@85.85,41.6 86.05,41.4 U23.2@87.386,41.4
NetR159_1: R159.1 U23.3 | length 1.7
  L1 - Top Layer w0.125: R159.1@85.85,40.6 86.15,40.9 U23.3@87.386,40.9
NetR169_1: R169.1 U24.8 | length 2.3
  L1 - Top Layer w0.125: U24.8@135.6,26.31 R169.1@135.6,28.65
NetR170_1: R170.1 U24.9 | length 2.3
  L1 - Top Layer w0.125: U24.9@134.4,26.31 R170.1@134.4,28.65
NetR172_1: R172.1 R175.1 U24.20 | length 7.1
  L1 - Top Layer w0.125: R175.1@121,16.6 R172.1@122.3,16.6 124.9,16.6 126.07,17.77 U24.20@127.62,17.77
NetR172_2: R172.2 Y7.1 | length 1.5
  L1 - Top Layer w0.125: R172.2@122.3,15.7 122.6,15.4 Y7.1@122.6,14.3
NetR174_1: R174.1 U24.2 | length 2
  L1 - Top Layer w0.3: R174.1@142.65,28.2 142.8,28.05 U24.2@142.8,26.31
NetR175_2: R175.2 Y8.1 | length 1.4
  L1 - Top Layer w0.125: Y8.1@120.95,14.3 121,14.35 R175.2@121,15.7
NetR208_1: R208.1 TP5.1 | length 5.2
  L1 - Top Layer w0.125: TP5.1@93.2,89.3 93.7,89.8 v1(93.7,90.5)
  L4 - Bottom Layer w0.125: v1(93.7,90.5) R208.1@93.7,94.25
NetR209_1: R209.1 TP6.1 | length 2
  L1 - Top Layer w0.125: TP6.1@94.5,89.3 94.7,89.5 v1(94.7,90.3)
  L4 - Bottom Layer w0.125: R209.1@94.5,91.15 94.5,90.5 v1(94.7,90.3)
NetR210_1: R210.1 TP7.1 | length 5.2
  L1 - Top Layer w0.125: v1(95.4,90.7) 95.8,90.3 TP7.1@95.8,89.3
  L4 - Bottom Layer w0.125: v1(95.4,90.7) 95.4,94.15 R210.1@95.5,94.25
NetR211_1: R211.1 TP8.1 | length 2.3
  L1 - Top Layer w0.125: v1(96.4,90.1) 96.4,90 TP8.1@97.1,89.3
  L4 - Bottom Layer w0.125: R211.1@96.3,91.25 96.3,90.2 v1(96.4,90.1)
NetR235_1: R235.1 R238.2 U27.B7 | length 12
  L1 - Top Layer w0.125: R235.1@11.625,89.6 11.625,88.7 12.85,87.475 14.35,87.475 17.425,84.4 18.475,84.4 18.675,84.6 18.675,84.95 19.075,85.35 U27.B7@19.075,85.6
  L1 - Top Layer w0.3: R235.1@11.625,89.6 R238.2@12.675,89.6
NetR239_2: R239.2 U27.C9 | length 4.1
  L1 - Top Layer w0.1: 19.471,88 19.471,87.854 19.875,87.45 U27.C9@19.875,87.2
  L1 - Top Layer w0.125: 19.471,88 19.471,88.354 19.413,88.413 19.413,90.288 R239.2@19.975,90.85
NetR242_1: R242.1 U27.H7 | length 3.7
  L1 - Top Layer w0.125: U27.H7@23.875,85.6 24.275,86 25.875,86 26.025,86.15 R242.1@27.375,86.15
NetR243_1: R243.1 U27.K8 | length 3.4
  L1 - Top Layer w0.125: U27.K8@25.475,86.4 25.675,86.6 26.475,86.6 26.675,86.8 27.825,86.8 R243.1@28.475,86.15
NetR244_1: R244.1 U27.H8 U27.K7 | length 3.7
  L1 - Top Layer w0.25: U27.H8@23.875,86.4 24.272,86.796 v3(24.272,86.801) ; U27.K7@25.475,85.6 26.082,85.6 v3(26.151,85.531)
  L4 - Bottom Layer w0.25: v3(24.272,86.801) 25.542,85.531 v3(26.151,85.531)
NetR245_2: R245.2 U27.D8 | length 4.8
  L1 - Top Layer w0.125: U27.D8@20.675,86.4 21.075,86.8 21.075,89.35 21.2,89.475 21.2,90.225 20.975,90.45 R245.2@20.975,90.85
NetR247_2: R247.2 U27.D1 | length 2.9
  L1 - Top Layer w0.125: U27.D1@20.675,80.8 20.675,78.725 v1(20.7,78.7)
  L4 - Bottom Layer w0.125: v1(20.7,78.7) 20.7,79 R247.2@21.05,79.35
NetR248_2: R248.2 U27.C1 | length 2.8
  L1 - Top Layer w0.125: U27.C1@19.875,80.8 19.875,78.725 v1(19.9,78.7)
  L4 - Bottom Layer w0.125: v1(19.9,78.7) 19.9,79.2 R248.2@20.05,79.35
NetR251_1: R251.1 Y10.3 | length 1.4
  L1 - Top Layer w0.125: R251.1@10.35,80.625 Y10.3@10.35,82.075
NetR252_2: R252.2 U29.5 | length 1.2
  L4 - Bottom Layer w0.125: R252.2@16.875,104.575 16.875,103.425 U29.5@16.925,103.375
NetR254_2: R254.2 U29.4 | length 1.2
  L4 - Bottom Layer w0.125: U29.4@14.275,103.375 R254.2@14.275,104.575
NetR266_2: R266.2 U30.5 | length 1.4
  L4 - Bottom Layer w0.125: U30.5@10.85,106.975 12.225,106.975 R266.2@12.25,107
NetR268_2: R268.2 U30.4 | length 1.4
  L4 - Bottom Layer w0.125: U30.4@10.85,109.625 12.225,109.625 R268.2@12.25,109.6
NRST_3U: J18.4 R235.2 | length 7.6
  L1 - Top Layer w0.125: J18.4@3.625,90.73 9.595,90.73 R235.2@10.725,89.6
NRST_PB25: J15.47 R34.1 R130.2 U5.E2 U6.4 U24.7 | length 237.1
  L1 - Top Layer w0.125: R34.1@34.4,57.65 34.4,57 34.75,56.65 35.88,56.65 36.65,55.88 U6.4@36.65,55.415 ; v1(38.5,47.475) 39.85,47.475 42.85,44.475 81.875,44.475 85.625,48.225 98.6,48.225 98.925,47.9 v3(98.925,47.6) 98.925,47.075 103.325,42.675 v3(136.5,42.675) v3@136.575,42.6 ; v3(67.5,25.575) 70.44,25.575 R130.2@70.565,25.7 ; U5.E2@76.725,70.725 77.049,70.401 79.999,70.401 81.3,69.1 81.3,68.3 81.9,67.7 81.9,67 82.2,66.7 83.93,66.7 84.1,66.87 85.93,66.87 90.3,62.5 v1(99.7,62.5) ; U24.7@136.8,26.31 v3(136.8,28)
  L4 - Bottom Layer w0.125: v1(35.575,56.65) 35.8,56.425 35.8,50.175 v1(38.5,47.475) ; v3(67.5,25.575) v3(67.5,44.475) ; v3(98.925,47.6) 98.925,50.15 99.475,50.7 99.7,50.925 v1(99.7,62.5) 99.4,62.8 99.4,85.7 99.6,85.9 99.6,97.1 100,97.5 J15.47@100,100.159 ; v3@136.5,42.725 136.8,42.425 v3(136.8,28)
PA02: R31.2 R32.2 U5.P1 | length 18
  L1 - Top Layer w0.125: U5.P1@77.375,76.575 87.425,76.575 R31.2@92.35,81.5 R32.2@92.35,82.5
PA03: R38.2 R39.2 U5.L3 | length 19.9
  L1 - Top Layer w0.125: U5.L3@76.075,74.625 76.394,74.944 v4@76.394,74.947
  L2 - GND w0.125: v4(76.4,74.95) v4@76.403,74.947
  L4 - Bottom Layer w0.125: v4@76.418,74.968 v4(76.4,74.95) 78.775,74.95 79.625,75.8 88.7,75.8 89.3,76.4 89.3,77 92.3,80 R39.2@92.35,80 R38.2@92.35,81
PA04: R40.2 R41.2 U5.N1 | length 17.8
  L1 - Top Layer w0.125: U5.N1@77.375,75.925 88.775,75.925 R40.2@92.35,79.5 R41.2@92.35,80.5 R41.2@92.125,80.725
PA07: R42.2 R43.2 U5.K6 | length 20.9
  L1 - Top Layer w0.125: U5.K6@74.125,73.975 v4(74.45,74.3)
  L4 - Bottom Layer w0.1: 75.009,74.625 76.491,74.625
  L4 - Bottom Layer w0.125: v4(74.45,74.3) 74.775,74.625 75.009,74.625 ; 76.491,74.625 79.2,74.625 79.975,75.4 89.75,75.4 R43.2@92.35,78 R42.2@92.35,79
PA08: R44.2 R45.2 U5.M1 | length 16.1
  L1 - Top Layer w0.125: U5.M1@77.375,75.275 91.275,75.275 91.5,75.5 R44.2@92.35,75.5 R45.2@92.35,76.5
PA11: R46.2 R50.2 R51.2 U5.H7 | length 23.9
  L1 - Top Layer w0.125: U5.H7@73.475,72.675 v4(73.8,72.35)
  L4 - Bottom Layer w0.125: v4(73.8,72.35) 73.8,72.7 74.2,73.1 81,73.1 81.6,73.7 89.65,73.7 R46.2@92.35,71 ; R51.2@92.351,69 R50.2@92.351,72
PA12: R52.2 R53.2 R54.2 U5.L1 | length 18.3
  L1 - Top Layer w0.125: U5.L1@77.375,74.625 89.226,74.625 R52.2@92.351,71.5 ; R53.2@92.351,70.5 R52.2@92.351,71.5 ; R54.2@92.351,72.5 R52.2@92.351,71.5
PA13: R55.2 R56.2 R57.2 U5.J6 | length 22.3
  L1 - Top Layer w0.125: U5.J6@74.125,73.325 v4(74.45,73.65)
  L4 - Bottom Layer w0.1: 75.009,73.975 76.491,73.975
  L4 - Bottom Layer w0.125: v4(74.45,73.65) 74.775,73.975 75.009,73.975 ; 76.491,73.975 76.875,73.975 77.1,74.2 79.6,74.2 80.4,75 90.6,75 91.6,76 R55.2@92.35,76 ; R57.2@92.35,74 R55.2@92.35,76 ; R56.2@92.35,77 R55.2@92.35,76
PA14: R58.2 R59.2 U5.K1 | length 18.2
  L1 - Top Layer w0.125: U5.K1@77.375,73.975 86.876,73.975 R58.2@92.351,68.5 R59.2@92.351,69.5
